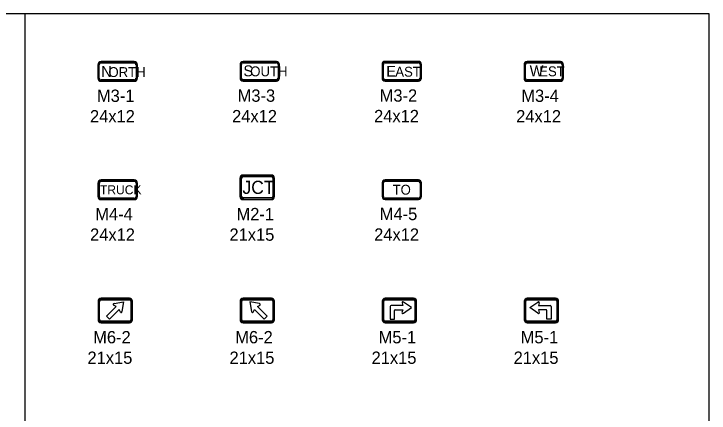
# Model space of a CAD drawing. Extents: x 1458 to 4498, y 17709 to 24109.
# Drawn here: x 3652 to 4498, y 21423 to 21909 of the extents above; entities that cross this region are included whole.
import ezdxf

# ---------------------------------------------------------------- set-up
doc = ezdxf.new("R2010")
doc.units = 0
doc.layers.add('P_ODOT_PLAN_TBlock', color=7, linetype='Continuous')
doc.layers.add('P_TRAF_TCP_General', color=7, linetype='Continuous')

msp = doc.modelspace()

# ---------------------------------------------------------------- linework, layer by layer
at = {"layer": 'P_ODOT_PLAN_TBlock'}
msp.add_line((3665.28, 21909.14), (3665.28, 20667.08), dxfattribs=at)
at = {"layer": 'P_TRAF_TCP_General'}
for p, q in [((3798.42, 21851.09), (3757.94, 21851.09)), ((3798.42, 21850.34), (3757.94, 21850.34)), ((3971.49, 21851.24), (3931.01, 21851.24)), ((3971.49, 21850.49), (3931.01, 21850.49)), ((4144.38, 21851.35), (4103.9, 21851.35)), ((4144.38, 21850.6), (4103.9, 21850.6)), ((4317.37, 21851.07), (4276.89, 21851.07)), ((4317.37, 21850.32), (4276.89, 21850.32)), ((3754.19, 21847.34), (3754.19, 21830.84)), ((3754.94, 21847.34), (3754.94, 21830.84)), ((3755.82, 21830.84), (3755.82, 21847.34)), ((3757.94, 21849.46), (3798.42, 21849.46)), ((3800.55, 21847.34), (3800.55, 21830.84)), ((3801.42, 21830.84), (3801.42, 21847.34)), ((3802.17, 21830.84), (3802.17, 21847.34)), ((3927.26, 21847.49), (3927.26, 21831)), ((3928.01, 21847.49), (3928.01, 21831)), ((3928.88, 21831), (3928.88, 21847.49)), ((3931.01, 21849.61), (3971.49, 21849.61)), ((3973.61, 21847.49), (3973.61, 21831)), ((3974.49, 21831), (3974.49, 21847.49)), ((3975.24, 21831), (3975.24, 21847.49)), ((4100.15, 21847.61), (4100.15, 21831.11)), ((4100.9, 21847.61), (4100.9, 21831.11)), ((4101.78, 21831.11), (4101.78, 21847.61)), ((4103.9, 21849.73), (4144.38, 21849.73)), ((4146.51, 21847.61), (4146.51, 21831.11)), ((4147.38, 21831.11), (4147.38, 21847.61)), ((4148.13, 21831.11), (4148.13, 21847.61)), ((4273.14, 21847.32), (4273.14, 21830.83)), ((4273.89, 21847.32), (4273.89, 21830.83)), ((4274.77, 21830.83), (4274.77, 21847.32)), ((4276.89, 21849.45), (4317.37, 21849.45)), ((4319.5, 21847.32), (4319.5, 21830.83)), ((4320.37, 21830.83), (4320.37, 21847.32)), ((4321.12, 21830.83), (4321.12, 21847.32)), ((3757.94, 21827.85), (3757.94, 21828.72)), ((3757.94, 21827.1), (3798.42, 21827.1)), ((3798.42, 21828.72), (3757.95, 21828.72)), ((3757.95, 21828.72), (3757.95, 21827.85)), ((3757.95, 21827.85), (3798.42, 21827.85)), ((3931.01, 21828), (3931.01, 21828.87)), ((3971.49, 21828.87), (3931.01, 21828.87)), ((3931.01, 21828.87), (3931.01, 21828)), ((3931.01, 21828), (3971.49, 21828)), ((3931.01, 21827.25), (3971.49, 21827.25)), ((4103.9, 21828.11), (4103.9, 21828.99)), ((4103.9, 21827.36), (4144.38, 21827.36)), ((4144.38, 21828.99), (4103.91, 21828.99)), ((4103.91, 21828.99), (4103.91, 21828.11)), ((4103.91, 21828.11), (4144.38, 21828.11)), ((4276.89, 21827.83), (4276.89, 21828.71)), ((4276.89, 21827.08), (4317.37, 21827.08)), ((4317.37, 21828.71), (4276.9, 21828.71)), ((4276.9, 21828.71), (4276.9, 21827.83)), ((4276.9, 21827.83), (4317.37, 21827.83)), ((3798.51, 21707.01), (3758.02, 21707.01)), ((3798.51, 21706.26), (3758.02, 21706.26)), ((3927.18, 21709.27), (3927.18, 21686.78)), ((3927.93, 21709.27), (3927.93, 21686.78)), ((3929.18, 21686.78), (3929.18, 21709.27)), ((3965.41, 21713.02), (3930.93, 21713.02)), ((3965.41, 21712.27), (3930.93, 21712.27)), ((3930.93, 21711.02), (3965.41, 21711.02)), ((3967.16, 21709.27), (3967.16, 21686.78)), ((3968.41, 21686.78), (3968.41, 21709.27)), ((3969.16, 21686.78), (3969.16, 21709.27)), ((4144.46, 21707.13), (4103.98, 21707.13)), ((4144.46, 21706.38), (4103.98, 21706.38)), ((3754.27, 21703.26), (3754.27, 21686.77)), ((3755.02, 21703.26), (3755.02, 21686.77)), ((3755.9, 21686.77), (3755.9, 21703.26)), ((3758.02, 21705.38), (3798.51, 21705.38)), ((3800.63, 21703.26), (3800.63, 21686.77)), ((3801.5, 21686.77), (3801.5, 21703.26)), ((3802.25, 21686.77), (3802.25, 21703.26)), ((4100.23, 21703.38), (4100.23, 21686.88)), ((4100.98, 21703.38), (4100.98, 21686.88)), ((4101.85, 21686.88), (4101.85, 21703.38)), ((4103.98, 21705.5), (4144.46, 21705.5)), ((4146.59, 21703.38), (4146.59, 21686.88)), ((4147.46, 21686.88), (4147.46, 21703.38)), ((4148.21, 21686.88), (4148.21, 21703.38)), ((3758.02, 21683.77), (3758.02, 21684.64)), ((3758.02, 21683.02), (3798.51, 21683.02)), ((3798.51, 21684.64), (3758.03, 21684.64)), ((3758.03, 21684.64), (3758.03, 21683.77)), ((3758.03, 21683.77), (3798.51, 21683.77)), ((3930.93, 21683.78), (3930.93, 21685.03)), ((3930.93, 21683.03), (3965.41, 21683.03)), ((3965.41, 21685.03), (3930.94, 21685.03)), ((3930.94, 21685.03), (3930.94, 21683.78)), ((3930.94, 21683.78), (3965.41, 21683.78)), ((4103.98, 21683.88), (4103.98, 21684.76)), ((4103.98, 21683.14), (4144.46, 21683.14)), ((4144.46, 21684.76), (4103.99, 21684.76)), ((4103.99, 21684.76), (4103.99, 21683.88)), ((4103.99, 21683.88), (4144.46, 21683.88)), ((3792.51, 21563.08), (3758.03, 21563.08)), ((3792.51, 21562.33), (3758.03, 21562.33)), ((3792.51, 21562.33), (3758.03, 21562.33)), ((3965.49, 21563.08), (3931.01, 21563.08)), ((3965.49, 21562.33), (3931.01, 21562.33)), ((3965.49, 21562.33), (3931.01, 21562.33)), ((4138.47, 21563.08), (4103.99, 21563.08)), ((4138.47, 21562.33), (4103.99, 21562.33)), ((4138.47, 21562.33), (4103.99, 21562.33)), ((4311.45, 21563.08), (4276.97, 21563.08)), ((4311.45, 21562.33), (4276.97, 21562.33)), ((4311.45, 21562.33), (4276.97, 21562.33)), ((3754.28, 21559.33), (3754.28, 21536.84)), ((3755.03, 21559.33), (3755.03, 21536.84)), ((3755.03, 21559.33), (3755.03, 21536.84)), ((3756.28, 21536.84), (3756.28, 21559.33)), ((3758.03, 21561.08), (3792.51, 21561.08)), ((3776.22, 21553.02), (3773.13, 21554.7)), ((3773.84, 21556.4), (3785.5, 21558.58)), ((3785.5, 21558.58), (3783.45, 21546.77)), ((3794.26, 21559.33), (3794.26, 21536.84)), ((3795.51, 21536.84), (3795.51, 21559.33)), ((3795.51, 21536.84), (3795.51, 21559.33)), ((3796.26, 21536.84), (3796.26, 21559.33)), ((3927.26, 21559.33), (3927.26, 21536.84)), ((3928.01, 21559.33), (3928.01, 21536.84)), ((3928.01, 21559.33), (3928.01, 21536.84)), ((3929.26, 21536.84), (3929.26, 21559.33)), ((3931.01, 21561.08), (3965.49, 21561.08)), ((3939.23, 21558.58), (3941.28, 21546.77)), ((3950.9, 21556.4), (3939.23, 21558.58)), ((3948.51, 21553.02), (3951.61, 21554.7)), ((3967.24, 21559.33), (3967.24, 21536.84)), ((3968.49, 21536.84), (3968.49, 21559.33)), ((3968.49, 21536.84), (3968.49, 21559.33)), ((3969.24, 21536.84), (3969.24, 21559.33)), ((4100.24, 21559.33), (4100.24, 21536.84)), ((4100.99, 21559.33), (4100.99, 21536.84)), ((4100.99, 21559.33), (4100.99, 21536.84)), ((4102.24, 21536.84), (4102.24, 21559.33)), ((4103.99, 21561.08), (4138.47, 21561.08)), ((4125.47, 21554.2), (4111.33, 21554.2)), ((4124.47, 21557.57), (4125.47, 21554.19)), ((4135.96, 21551.56), (4126.17, 21558.27)), ((4140.22, 21559.33), (4140.22, 21536.84)), ((4141.47, 21536.84), (4141.47, 21559.33)), ((4141.47, 21536.84), (4141.47, 21559.33)), ((4142.22, 21536.84), (4142.22, 21559.33)), ((4273.22, 21559.33), (4273.22, 21536.84)), ((4273.97, 21559.33), (4273.97, 21536.84)), ((4273.97, 21559.33), (4273.97, 21536.84)), ((4275.22, 21536.84), (4275.22, 21559.33)), ((4276.97, 21561.08), (4311.45, 21561.08)), ((4280.2, 21551.56), (4289.99, 21558.27)), ((4291.69, 21557.57), (4290.69, 21554.19)), ((4290.69, 21554.2), (4304.83, 21554.2)), ((4313.2, 21559.33), (4313.2, 21536.84)), ((4314.45, 21536.84), (4314.45, 21559.33)), ((4314.45, 21536.84), (4314.45, 21559.33)), ((4315.2, 21536.84), (4315.2, 21559.33)), ((3764.48, 21541.28), (3776.22, 21553.02)), ((3779.93, 21549.31), (3768.2, 21537.57)), ((3781.66, 21546.16), (3779.93, 21549.31)), ((3943.07, 21546.16), (3944.8, 21549.31)), ((3944.8, 21549.31), (3956.54, 21537.57)), ((3960.25, 21541.28), (3948.51, 21553.02)), ((4110.08, 21552.95), (4110.08, 21537.33)), ((4115.33, 21537.33), (4115.33, 21548.19)), ((4116.08, 21548.94), (4125.47, 21548.94)), ((4125.47, 21548.94), (4124.46, 21545.49)), ((4126.16, 21544.66), (4135.96, 21551.56)), ((4290, 21544.66), (4280.2, 21551.56)), ((4300.08, 21548.94), (4290.69, 21548.94)), ((4290.69, 21548.94), (4291.7, 21545.49)), ((4291.7, 21545.36), (4291.7, 21545.36)), ((4300.83, 21537.33), (4300.83, 21548.19)), ((4306.08, 21552.95), (4306.08, 21537.33)), ((3768.2, 21537.57), (3764.48, 21541.28)), ((3956.54, 21537.57), (3960.26, 21541.28)), ((4110.08, 21537.33), (4115.33, 21537.33)), ((4306.08, 21537.33), (4300.83, 21537.33)), ((3758.03, 21533.84), (3758.03, 21535.09)), ((3758.03, 21533.84), (3792.51, 21533.84)), ((3758.03, 21533.09), (3792.51, 21533.09)), ((3792.51, 21535.09), (3758.04, 21535.09)), ((3758.04, 21535.09), (3758.04, 21533.84)), ((3758.04, 21533.84), (3792.51, 21533.84)), ((3931.01, 21533.84), (3931.01, 21535.09)), ((3931.01, 21533.84), (3965.49, 21533.84)), ((3931.01, 21533.09), (3965.49, 21533.09)), ((3965.49, 21535.09), (3931.02, 21535.09)), ((3931.02, 21535.09), (3931.02, 21533.84)), ((3931.02, 21533.84), (3965.49, 21533.84)), ((4103.99, 21533.84), (4103.99, 21535.09)), ((4103.99, 21533.84), (4138.47, 21533.84)), ((4103.99, 21533.09), (4138.47, 21533.09)), ((4138.47, 21535.09), (4104, 21535.09)), ((4104, 21535.09), (4104, 21533.84)), ((4104, 21533.84), (4138.47, 21533.84)), ((4276.97, 21533.84), (4276.97, 21535.09)), ((4276.97, 21533.84), (4311.45, 21533.84)), ((4276.97, 21533.09), (4311.45, 21533.09)), ((4311.45, 21535.09), (4276.98, 21535.09)), ((4276.98, 21535.09), (4276.98, 21533.84)), ((4276.98, 21533.84), (4311.45, 21533.84))]:
    msp.add_line(p, q, dxfattribs=at)
msp.add_lwpolyline([(4498.44, 21909.14), (1458.44, 21909.14), (1458.44, 19909.14), (4498.44, 19909.14)], close=True, dxfattribs=at)
for centre, radius, start, end in [((3757.94, 21847.34), 3.75, 90, 180), ((3757.94, 21847.34), 3, 90, 180), ((3798.42, 21847.34), 3.75, 0, 90), ((3798.42, 21847.34), 3, 0, 90), ((3931.01, 21847.49), 3.75, 90, 180), ((3931.01, 21847.49), 3, 90, 180), ((3971.49, 21847.49), 3.75, 0, 90), ((3971.49, 21847.49), 3, 0, 90), ((4103.9, 21847.61), 3.75, 90, 180), ((4103.9, 21847.61), 3, 90, 180), ((4144.38, 21847.61), 3.75, 0, 90), ((4144.38, 21847.61), 3, 0, 90), ((4276.89, 21847.32), 3.75, 90, 180), ((4276.89, 21847.32), 3, 90, 180), ((4317.37, 21847.32), 3.75, 0, 90), ((4317.37, 21847.32), 3, 0, 90), ((3757.94, 21847.34), 2.12, 90, 180), ((3798.42, 21847.34), 2.12, 0, 90), ((3931.01, 21847.49), 2.12, 90, 180), ((3971.49, 21847.49), 2.12, 0, 90), ((4103.9, 21847.61), 2.12, 90, 180), ((4144.38, 21847.61), 2.12, 0, 90), ((4276.89, 21847.32), 2.12, 90, 180), ((4317.37, 21847.32), 2.12, 0, 90), ((3757.94, 21830.84), 3.75, 180, 270), ((3757.94, 21830.84), 3, 180, 270), ((3757.94, 21830.84), 2.12, 180, 270), ((3798.42, 21830.84), 3, 270, 0), ((3798.42, 21830.84), 2.12, 270, 0), ((3798.42, 21830.84), 3.75, 270, 0), ((3931.01, 21831), 3.75, 180, 270), ((3931.01, 21831), 3, 180, 270), ((3931.01, 21831), 2.12, 180, 270), ((3971.49, 21831), 3, 270, 0), ((3971.49, 21831), 2.12, 270, 0), ((3971.49, 21831), 3.75, 270, 0), ((4103.9, 21831.11), 3.75, 180, 270), ((4103.9, 21831.11), 3, 180, 270), ((4103.9, 21831.11), 2.12, 180, 270), ((4144.38, 21831.11), 3, 270, 0), ((4144.38, 21831.11), 2.12, 270, 0), ((4144.38, 21831.11), 3.75, 270, 0), ((4276.89, 21830.83), 3.75, 180, 270), ((4276.89, 21830.83), 3, 180, 270), ((4276.89, 21830.83), 2.12, 180, 270), ((4317.37, 21830.83), 3, 270, 0), ((4317.37, 21830.83), 2.12, 270, 0), ((4317.37, 21830.83), 3.75, 270, 0), ((3758.02, 21703.26), 3.75, 90, 180), ((3758.02, 21703.26), 3, 90, 180), ((3798.51, 21703.26), 3.75, 0, 90), ((3798.51, 21703.26), 3, 0, 90), ((3930.93, 21709.27), 3.75, 90, 180), ((3930.93, 21709.27), 3, 90, 180), ((3930.93, 21709.27), 1.75, 90, 180), ((3965.41, 21709.27), 3.75, 0, 90), ((3965.41, 21709.27), 3, 0, 90), ((3965.41, 21709.27), 1.75, 0, 90), ((4103.98, 21703.38), 3.75, 90, 180), ((4103.98, 21703.38), 3, 90, 180), ((4144.46, 21703.38), 3.75, 0, 90), ((4144.46, 21703.38), 3, 0, 90), ((3758.02, 21703.26), 2.12, 90, 180), ((3798.51, 21703.26), 2.12, 0, 90), ((4103.98, 21703.38), 2.12, 90, 180), ((4144.46, 21703.38), 2.12, 0, 90), ((3758.02, 21686.77), 3.75, 180, 270), ((3758.02, 21686.77), 3, 180, 270), ((3758.02, 21686.77), 2.12, 180, 270), ((3798.51, 21686.77), 3, 270, 0), ((3798.51, 21686.77), 2.12, 270, 0), ((3798.51, 21686.77), 3.75, 270, 0), ((3930.93, 21686.78), 3.75, 180, 270), ((3930.93, 21686.78), 3, 180, 270), ((3930.93, 21686.78), 1.75, 180, 270), ((3965.41, 21686.78), 3, 270, 0), ((3965.41, 21686.78), 1.75, 270, 0), ((3965.41, 21686.78), 3.75, 270, 0), ((4103.98, 21686.88), 3.75, 180, 270), ((4103.98, 21686.88), 3, 180, 270), ((4103.98, 21686.88), 2.12, 180, 270), ((4144.46, 21686.88), 3, 270, 0), ((4144.46, 21686.88), 2.12, 270, 0), ((4144.46, 21686.88), 3.75, 270, 0), ((3758.03, 21559.33), 3.75, 90, 180), ((3758.03, 21559.33), 3, 90, 180), ((3758.03, 21559.33), 3, 90, 180), ((3792.51, 21559.33), 3.75, 0, 90), ((3792.51, 21559.33), 3, 0, 90), ((3792.51, 21559.33), 3, 0, 90), ((3931.01, 21559.33), 3.75, 90, 180), ((3931.01, 21559.33), 3, 90, 180), ((3931.01, 21559.33), 3, 90, 180), ((3965.49, 21559.33), 3.75, 0, 90), ((3965.49, 21559.33), 3, 0, 90), ((3965.49, 21559.33), 3, 0, 90), ((4103.99, 21559.33), 3.75, 90, 180), ((4103.99, 21559.33), 3, 90, 180), ((4103.99, 21559.33), 3, 90, 180), ((4138.47, 21559.33), 3.75, 0, 90), ((4138.47, 21559.33), 3, 0, 90), ((4138.47, 21559.33), 3, 0, 90), ((4276.97, 21559.33), 3.75, 90, 180), ((4276.97, 21559.33), 3, 90, 180), ((4276.97, 21559.33), 3, 90, 180), ((4311.45, 21559.33), 3.75, 0, 90), ((4311.45, 21559.33), 3, 0, 90), ((4311.45, 21559.33), 3, 0, 90), ((3758.03, 21559.33), 1.75, 90, 180), ((3773.84, 21555.4), 1, 90, 224.50461), ((3792.51, 21559.33), 1.75, 0, 90), ((3931.01, 21559.33), 1.75, 90, 180), ((3950.9, 21555.4), 1, 315.49539, 90), ((3965.49, 21559.33), 1.75, 0, 90), ((4103.99, 21559.33), 1.75, 90, 180), ((4111.33, 21552.95), 1.25, 90, 180), ((4125.47, 21557.56), 1, 45, 179.50461), ((4138.47, 21559.33), 1.75, 0, 90), ((4276.97, 21559.33), 1.75, 90, 180), ((4290.69, 21557.56), 1, 0.49539, 135), ((4304.83, 21552.95), 1.25, 0, 90), ((4311.45, 21559.33), 1.75, 0, 90), ((3782.45, 21546.77), 1, 217.68986, 0), ((3942.28, 21546.77), 1, 180, 322.31014), ((4116.08, 21548.19), 0.75, 90, 180), ((4125.46, 21545.36), 1, 180.49539, 315), ((4290.71, 21545.36), 1, 225, 359.50461), ((4300.08, 21548.19), 0.75, 0, 90), ((3758.03, 21536.84), 3.75, 180, 270), ((3758.03, 21536.84), 3, 180, 270), ((3758.03, 21536.84), 3, 180, 270), ((3758.03, 21536.84), 1.75, 180, 270), ((3792.51, 21536.84), 3, 270, 0), ((3792.51, 21536.84), 3, 270, 0), ((3792.51, 21536.84), 1.75, 270, 0), ((3792.51, 21536.84), 3.75, 270, 0), ((3931.01, 21536.84), 3.75, 180, 270), ((3931.01, 21536.84), 3, 180, 270), ((3931.01, 21536.84), 3, 180, 270), ((3931.01, 21536.84), 1.75, 180, 270), ((3965.49, 21536.84), 3, 270, 0), ((3965.49, 21536.84), 3, 270, 0), ((3965.49, 21536.84), 1.75, 270, 0), ((3965.49, 21536.84), 3.75, 270, 0), ((4103.99, 21536.84), 3.75, 180, 270), ((4103.99, 21536.84), 3, 180, 270), ((4103.99, 21536.84), 3, 180, 270), ((4103.99, 21536.84), 1.75, 180, 270), ((4138.47, 21536.84), 3, 270, 0), ((4138.47, 21536.84), 3, 270, 0), ((4138.47, 21536.84), 1.75, 270, 0), ((4138.47, 21536.84), 3.75, 270, 0), ((4276.97, 21536.84), 3.75, 180, 270), ((4276.97, 21536.84), 3, 180, 270), ((4276.97, 21536.84), 3, 180, 270), ((4276.97, 21536.84), 1.75, 180, 270), ((4311.45, 21536.84), 3, 270, 0), ((4311.45, 21536.84), 3, 270, 0), ((4311.45, 21536.84), 1.75, 270, 0), ((4311.45, 21536.84), 3.75, 270, 0)]:
    msp.add_arc(centre, radius, start, end, dxfattribs=at)

# ---------------------------------------------------------------- texts
for s, height, p in [('N', 13.19, (3758.28, 21832.33)), ('ORTH', 11.995, (3766.95, 21832.33)), ('S', 13.19, (3931.32, 21833.21)), ('OUTH', 11.995, (3939.67, 21833.21)), ('E', 13.19, (4105.35, 21832.72)), ('AST', 11.995, (4116.27, 21832.72)), ('W', 13.19, (4279.96, 21833.16)), ('EST', 11.995, (4291.52, 21833.22)), ('M3-1', 14.994, (3752.97, 21802.02)), ('M3-3', 14.994, (3924.32, 21802.17)), ('M3-2', 14.994, (4097.27, 21802.29)), ('M3-4', 14.994, (4269.78, 21802.01)), ('24x12', 14.994, (3744.53, 21777.03)), ('24x12', 14.994, (3917.6, 21777.18)), ('24x12', 14.994, (4090.49, 21777.3)), ('24x12', 14.994, (4263.49, 21777.02)), ('JCT', 15.994, (3930.15, 21690.01)), ('TRUCK', 10.996, (3756.63, 21689.51)), ('TO', 11.995, (4112.96, 21689.13)), ('M4-4', 14.994, (3750.91, 21657.94)), ('M2-1', 14.994, (3922.95, 21657.96)), ('M4-5', 14.994, (4097.38, 21658.06)), ('24x12', 14.994, (3744.62, 21632.95)), ('21x15', 14.994, (3914.38, 21632.97)), ('24x12', 14.994, (4090.57, 21633.07)), ('M6-2', 14.994, (3748.4, 21508.1)), ('M6-2', 14.994, (3921.38, 21508.1)), ('M5-1', 14.994, (4096.01, 21508.1)), ('M5-1', 14.994, (4269, 21508.1)), ('21x15', 14.994, (3741.48, 21483.11)), ('21x15', 14.994, (3914.46, 21483.11)), ('21x15', 14.994, (4087.44, 21483.11)), ('21x15', 14.994, (4260.42, 21483.11))]:
    msp.add_text(s, height=height, dxfattribs=at).set_placement(p)

doc.saveas('drawing.dxf')
